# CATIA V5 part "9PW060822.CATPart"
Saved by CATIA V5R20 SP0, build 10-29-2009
Part number: 9PW060822
Revision: ANY
Definition: UNKNOWN
Nomenclature: 9PW060822
Source: Unknown
Bounding box of the stored display mesh (mm): x -124.5 to 0, y -9.384 to 3, z -4.1 to 4.1
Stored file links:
  C:\Users\Utente\Desktop\IO LAVORO\3D X SITO CF\CUMSA\3D files PW\pw060822\pw060822_ejection\9PW060822.CATPart
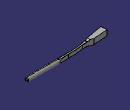
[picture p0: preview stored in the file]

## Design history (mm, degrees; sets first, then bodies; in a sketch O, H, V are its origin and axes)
Body1 "Chaflán1" (main body)
  Solid1: solid without history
